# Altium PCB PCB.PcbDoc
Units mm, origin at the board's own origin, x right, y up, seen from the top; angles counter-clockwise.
Board outline 41 x 25.36 mm, 2 copper layers (TOP, BOTTOM), stack 1.586 mm thick; 43 components, 23 nets, 113 pads, 47 vias.
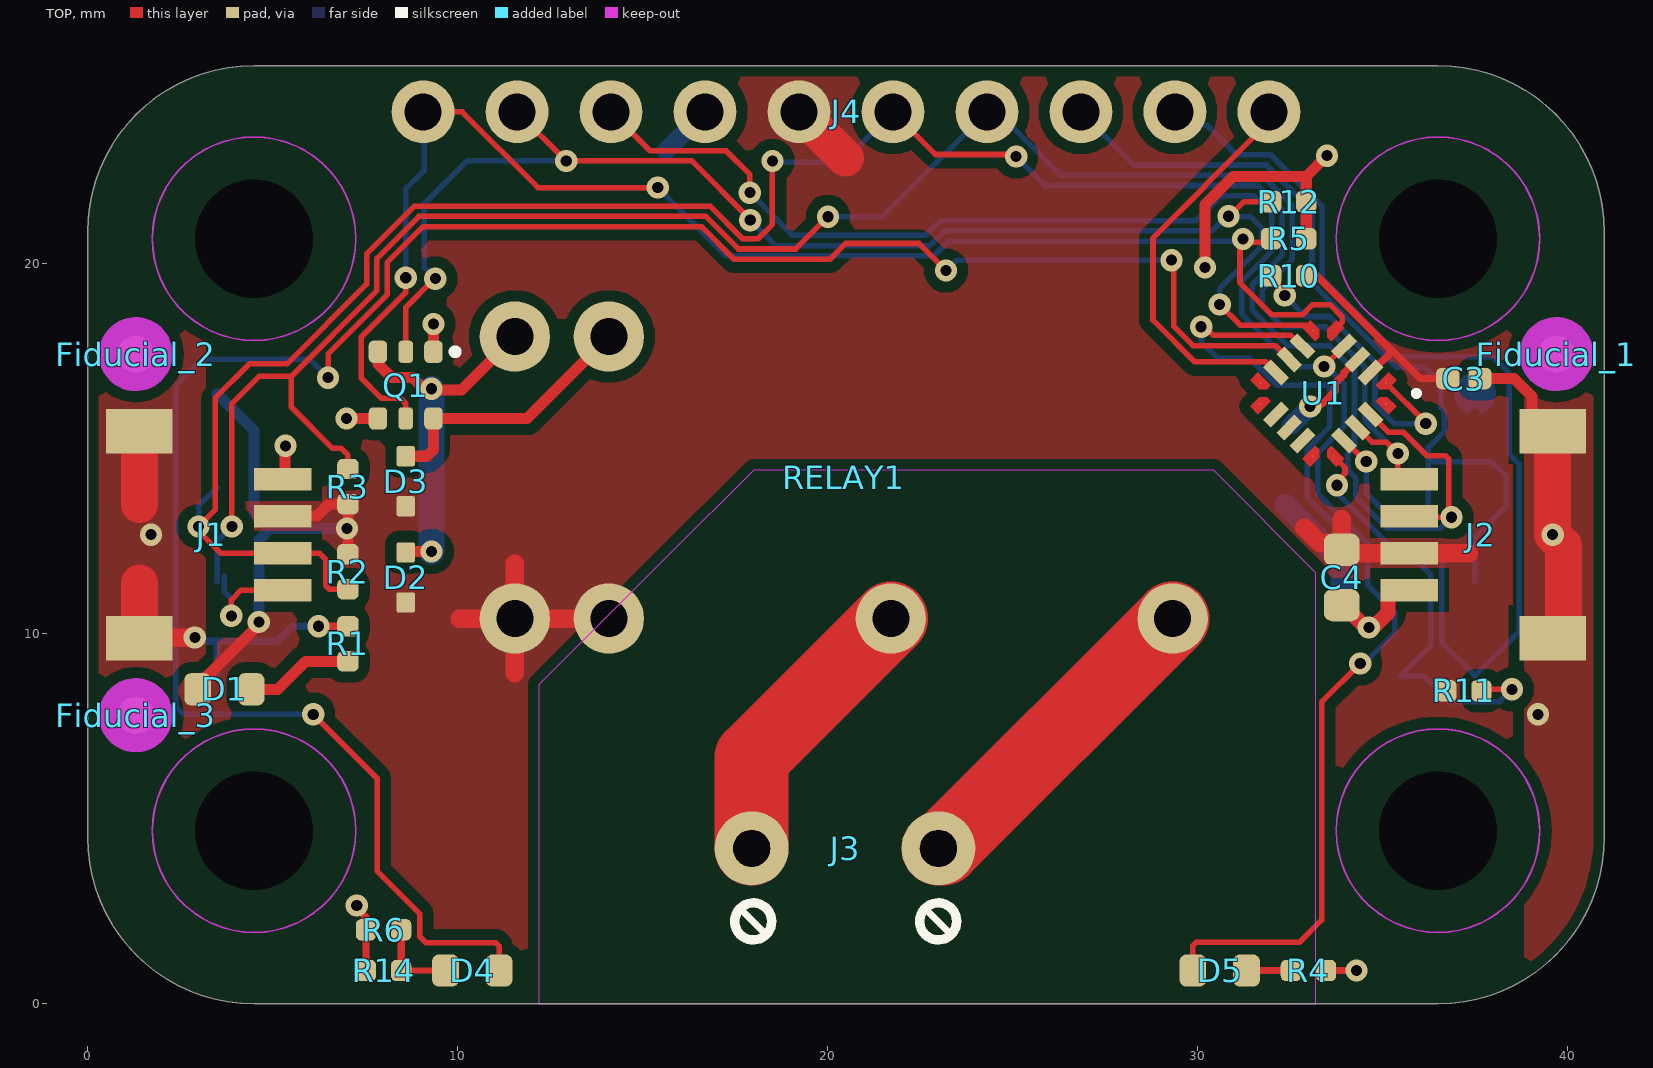
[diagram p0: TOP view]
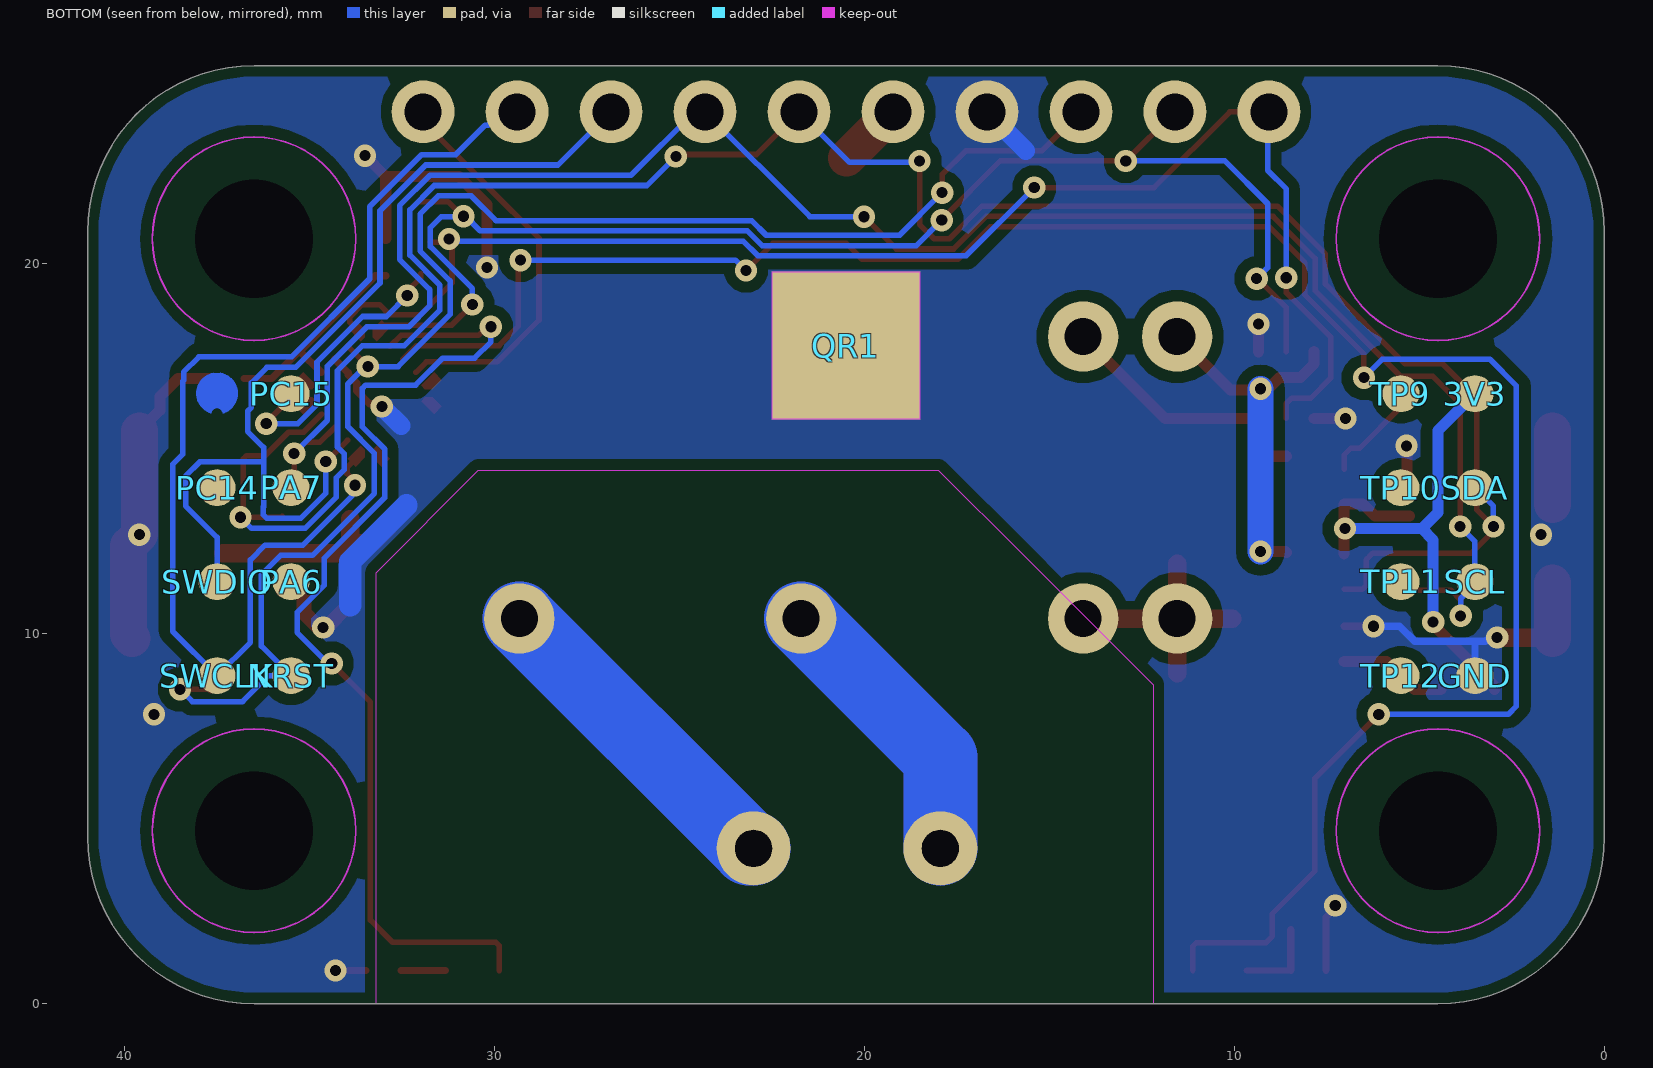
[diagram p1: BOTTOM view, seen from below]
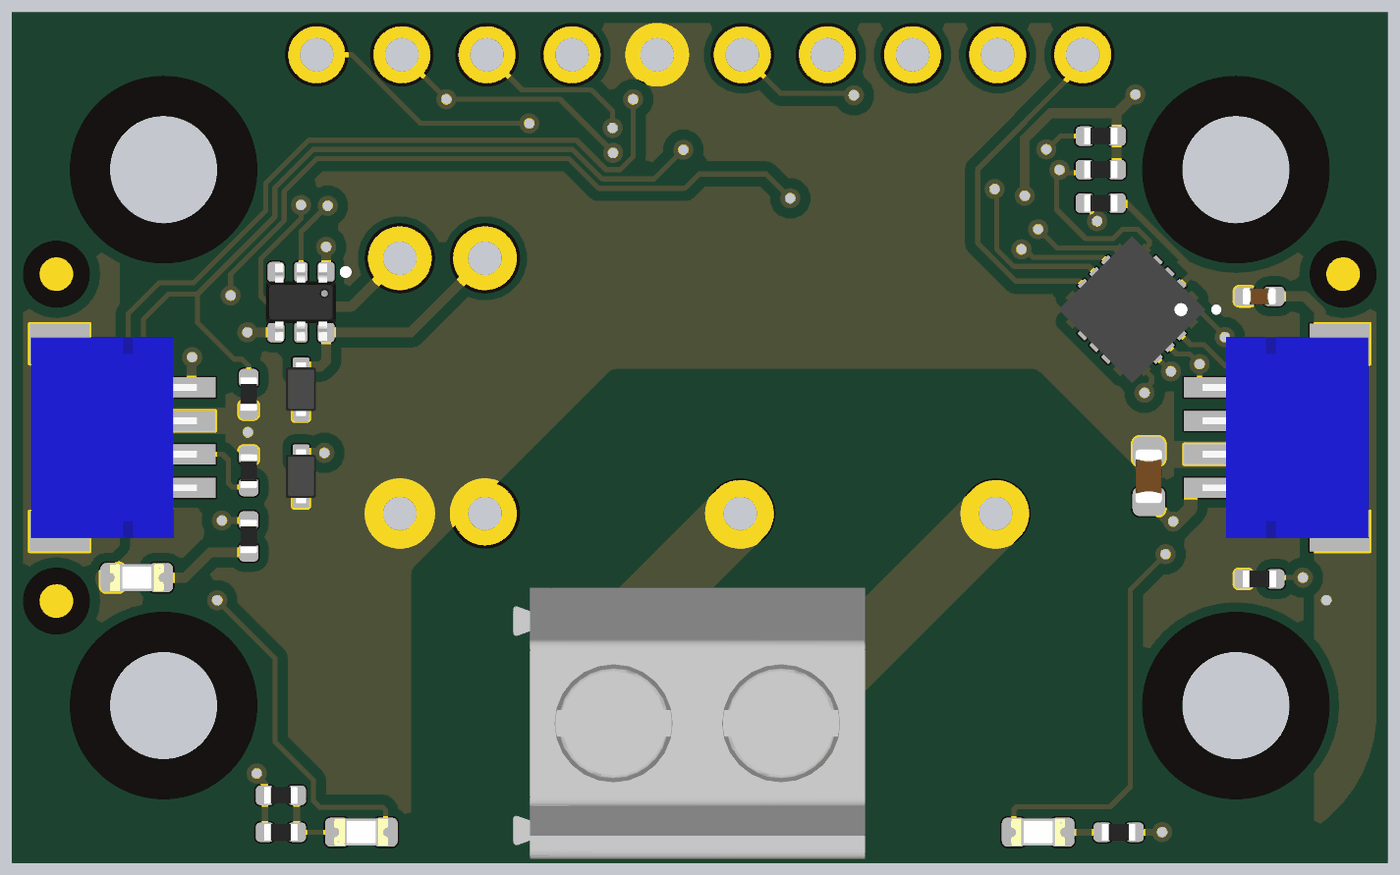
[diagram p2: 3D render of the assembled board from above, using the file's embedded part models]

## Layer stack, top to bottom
Top Solder: solder mask 0.01, Solder Resist, Dk 3.5
TOP: signal copper 0.018
Dielectric: core 1.55, FR-4, Dk 4.8
BOTTOM: signal copper 0.018
Bottom Solder: solder mask 0.01, Solder Resist, Dk 3.5

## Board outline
0,4.5 ccw(c4.5,4.5) 4.5,0 36.5,0 ccw(c36.5,4.5) 41,4.5 41,20.86 ccw(c36.5,20.86) 36.5,25.36 4.5,25.36 ccw(c4.5,20.86) 0,20.86

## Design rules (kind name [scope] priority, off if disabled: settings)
BoardOutlineClearance Mousebites [(ObjectKind = 'Pad') And (Name = 'Free-MOUSEBITE')] p1: gap=0 ignorepadtopadclearanceinfootprint=FALSE
BoardOutlineClearance Silks [(OnLayer('Top Overlay') OR OnLayer('Bottom Overlay'))] p2: gap=0 ignorepadtopadclearanceinfootprint=FALSE
BoardOutlineClearance [All] p3: gap=0.3 ignorepadtopadclearanceinfootprint=FALSE
Clearance CONTACTS_CLEARANCE [InNetClass('CONTACTS') vs NOT((ObjectKind = 'Region') And (Layer = 'MultiLayer'))] p1: gap=2 ignorepadtopadclearanceinfootprint=FALSE
Clearance COPPER_0.3mm [All] p2: gap=0.127 ignorepadtopadclearanceinfootprint=FALSE except(0.3: Arc-Fill Arc-Poly Arc-Region Track-Fill Track-Poly Track-Region SMDPad-Fill SMDPad-Poly SMDPad-Region THPad-Fill THPad-Poly THPad-Region Via-Fill Via-Poly Via-Region Fill-Fill Fill-Poly Fill-Region Poly-Poly Poly-Region Region-Region)
Clearance "Generic clearance 0.15mm" [All] p3: gap=0.15 ignorepadtopadclearanceinfootprint=FALSE
ComponentClearance [All] p1: gap=0.2 collisioncheckmode=3 verticalgap=0 showdistances=TRUE
DiffPairsRouting USB [InDifferentialPairClass('USB')] p1: maxlimit=0.15 minlimit=0.15 mostfreqgap=0.15 toplayer_minwidth=0.15 toplayer_maxwidth=0.21 toplayer_prefwidth=0.2 bottomlayer_minwidth=0.15 bottomlayer_maxwidth=0.21 bottomlayer_prefwidth=0.2 impedanceprofiledriven=TRUE impedanceprofileid={E6B00C31-4C8E-439C-824F-D2B2CDC26F9C} impedanceprofilevalue=90.000000 maxuncoupledlength=12.7
Height [All] p1: minheight=0 maxheight=30 prefheight=12.7
HoleSize [All] p1: absolutevalues=TRUE maxlimit=30 minlimit=0.3 maxpercent=80.000 minpercent=20.000
HoleToHoleClearance [All] p1: gap=0.25 allowstackedmicrovias=FALSE
MinimumAnnularRing [All] p1: minimumring=0.15
PlaneConnect [All] p1: pad.planeconnectstyle=Relief pad.reliefexpansion=0.508 pad.reliefentries=4 pad.reliefconductorwidth=0.254 pad.reliefairgap=0.254 via.planeconnectstyle=Direct via.reliefexpansion=0.508 via.reliefentries=4 via.reliefconductorwidth=0.254 via.reliefairgap=0.254
PolygonConnect PolygonConnect_QR [All] p1: connectstyle=Direct reliefconductorwidth=0.254 reliefentries=4 polygonreliefangle="90 Angle" airgapwidth=0.254
PolygonConnect [All] p2: thpad.connectstyle=Relief thpad.reliefconductorwidth=0.2 thpad.reliefentries=4 thpad.polygonreliefangle="90 Angle" thpad.airgapwidth=0.254 smdpad.connectstyle=Relief smdpad.reliefconductorwidth=0.2 smdpad.reliefentries=4 smdpad.polygonreliefangle="90 Angle" smdpad.airgapwidth=0.254 via.connectstyle=Direct via.reliefconductorwidth=0.254 via.reliefentries=4 via.polygonreliefangle="90 Angle" via.airgapwidth=0.254
RoomDefinition K36 [False vs False] p1: confinementstyle=ConfineIn formatcopy=TRUE lockcomponents=FALSE outline 4.642,2.629 7.942,2.629 7.942,-0.171 4.642,-0.171
RoomDefinition K_1 [False vs False] p2: confinementstyle=ConfineIn formatcopy=TRUE lockcomponents=FALSE outline 7.8,25.6 11.5,25.6 11.5,22.8 7.8,22.8
RoomDefinition TOP [InComponentClass('TOP')] p3: confinementstyle=ConfineIn formatcopy=TRUE lockcomponents=FALSE outline 42.1,5.4 49.2,5.4 49.2,22.3 42.1,22.3
RoutingVias StandardVias [All] p1: holewidth=0.3 width=0.6 viastyle="Through Hole" minholewidth=0.3 minwidth=0.6 maxholewidth=0.3 maxwidth=0.6
SMDToCorner [All] p1: distance=39370
SilkToSilkClearance [All] p1: silktosilkclearance=0.2
SilkToSolderMaskClearance [IsPad] p1: minsilkscreentomaskgap=0.15 clearancetoexposedcopper=TRUE
SolderMaskExpansion VIAtented [IsVia] p1: expansion=0.102 istentingtop=TRUE
SolderMaskExpansion [All] p2: expansion=0.05 istentingtop=FALSE
SupplyNets "Schematic Supply Nets_2" [InNet('+3V3')] p1: voltage=0.000
SupplyNets "Schematic Supply Nets" [InNet('GND')] p2: voltage=0.000
UnConnectedPin [All] p1:
UnRoutedNet [NOT WithinRoom('K36')] p1: checkbadconnections=TRUE
ViasUnderSMD [All] p1: allowed=FALSE
Width StandardTraces [All] p1: maxlimit=5 minlimit=0.15 preferedwidth=0.15 minimp=50.000000 maximp=50.000000 favimp=50.000000
21 further rules are at their usual default settings.

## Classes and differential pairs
net class CONTACTS: NetJ3_1 NetJ3_2
component class U_MICROCONTROLLER: C3 C4 R2 R3 R10 R11 U1
component class TOP: 3V3 D1 D2 D3 D4 D5 Fiducial_1 Fiducial_2 Fiducial_3 GND J1 J2 J3 J4 NRST PA6 PA7 PC14 PC15 Q1 QR1 R1 R4 R5 R6 R12 R14 RELAY1 SCL SDA SWCLK SWDIO TP9 TP10 TP11 TP12

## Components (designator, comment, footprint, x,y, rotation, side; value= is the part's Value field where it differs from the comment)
3V3 "Test point 1.00mm" TP-1.00MM 3.5,16.49 r90 bottom
C3 "0402B104K160CT" CAP-0402 37.2,16.9 r0 top value=100nF
C4 "GRM188R61C475KAAJD" CAP-0603 33.9,11.524 r90 top value=4.7µF
D1 "HSMG-C190" LEDC1608X80N-AK 3.7,8.5 r180 top
D2 "SBD52C05L01" "SOD523 NO POLARITY" 8.6,11.524 r270 top
D3 "SBD52C05L01" "SOD523 NO POLARITY" 8.6,14.124 r270 top
D4 "KPT-1608YC" LEDC1608X80N-AK 10.4,0.9 r0 top
D5 "XHY-STB0603SR" LEDC1608X80N-AK 30.6,0.9 r180 top
Fiducial_1 "Fiducial mark 1mm" "Fiducial mark 1mm-Footprint-1" 39.7,17.56 r270 top
Fiducial_2 "Fiducial mark 1mm" "Fiducial mark 1mm-Footprint-1" 1.3,17.56 r270 top
Fiducial_3 "Fiducial mark 1mm" "Fiducial mark 1mm-Footprint-1" 1.3,7.8 r270 top
GND "Test point 1.00mm" TP-1.00MM 3.5,8.87 r90 bottom
J1 "SM04B-SRSS-TB(LF)(SN)" SM04B-SRSS-TB(LF)(SN)-Footprint-1 3.337,12.68 r90 top locked
J2 "SM04B-SRSS-TB(LF)(SN)" SM04B-SRSS-TB(LF)(SN)-Footprint-1 37.663,12.68 r270 top locked
J3 "DG127-5.0-02P-13-00Z(H)" DG127-5.0-02P-14-00A(H) 20.5,4.2 r180 top
J4 "HEADER TH 2.54mm VERT. 1x010POS" "PIN HEADER 2.54mm VERT. 1x10POS" 20.5,24.11 r0 top locked
NRST "Test point 1.00mm" TP-1.00MM 35.5,8.87 r180 bottom
PA6 "Test point 1.00mm" TP-1.00MM 35.5,11.41 r180 bottom
PA7 "Test point 1.00mm" TP-1.00MM 35.5,13.95 r180 bottom
PC14 "Test point 1.00mm" TP-1.00MM 37.5,13.95 r180 bottom
PC15 "Test point 1.00mm" TP-1.00MM 35.5,16.49 r180 bottom
Q1 "2N7002PS,115" SOT363 8.6,16.724 r180 top
QR1 "QR CODE 4x4mm" "QR CODE 4x4mm" 20.5,17.793 r180 bottom
R1 "CRCW04021K00FKEDC" RES-0402 7.039,9.73 r270 top value=1k
R2 "RC0402FR-074K7L" RES-0402 7.039,11.68 r90 top value=4.7k
R3 "RC0402FR-074K7L" RES-0402 7.039,13.98 r270 top value=4.7k
R4 "CRCW04021K00FKEDC" RES-0402 33,0.9 r180 top value=1k
R5 "RC0402FR-074K7L" RES-0402 32.465,20.68 r0 top value=4.7k
R6 "CRCW04021K00FKEDC" RES-0402 8,2 r0 top value=1k
R10 "RC0402FR-074K7L" RES-0402 32.465,19.68 r180 top value=4.7k
R11 "RC0402FR-074K7L" RES-0402 37.2,8.46 r0 top value=4.7k
R12 "RC0402FR-074K7L" RES-0402 32.465,21.68 r0 top value=4.7k
R14 "CRCW04021K00FKEDC" RES-0402 8,0.9 r0 top value=1k
RELAY1 "HFE60/3-1HT-L2" HFE60/3-1HT-L2 20.5,14.224 r0 top locked
SCL "Test point 1.00mm" TP-1.00MM 3.5,11.41 r90 bottom
SDA "Test point 1.00mm" TP-1.00MM 3.5,13.95 r90 bottom
SWCLK "Test point 1.00mm" TP-1.00MM 37.5,8.87 r180 bottom
SWDIO "Test point 1.00mm" TP-1.00MM 37.5,11.41 r180 bottom
TP9 "Test point 1.00mm" TP-1.00MM 5.5,16.49 r0 bottom
TP10 "Test point 1.00mm" TP-1.00MM 5.5,13.95 r0 bottom
TP11 "Test point 1.00mm" TP-1.00MM 5.5,11.41 r0 bottom
TP12 "Test point 1.00mm" TP-1.00MM 5.5,8.87 r0 bottom
U1 "STM32C011F6U6TR" UFQFPN20 33.4,16.5 r225 top

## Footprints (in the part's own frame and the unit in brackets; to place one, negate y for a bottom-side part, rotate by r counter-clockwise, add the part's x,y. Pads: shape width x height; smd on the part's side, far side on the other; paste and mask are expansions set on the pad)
CAP-0402 [mm] "Chip Capacitor, 2-Leads, Body  0402 (in) 1005 (mm), IPC Medium Density"
  rrect52% 0.63x0.58 smd mask+0.05: 1(-0.435,0) 2(0.435,0)
  body extent -0.5,-0.25 0.5,0.25, height 0.5
CAP-0603 [mm] "Chip Capacitor, Body 0603 imperial,1.6x0.8mm, IPC High Density"
  rrect51% 0.87x0.97 smd mask+0.05: 1(-0.75,0) 2(0.75,0)
  body extent -0.8,-0.4 0.8,0.4, height 0.8
DG127-5.0-02P-14-00A(H) [mm]
  round 2 hole 1 mask+0.05: 1(-2.5,0) 2(2.55,0)
  silkscreen extent -2.99,1.47 3.01,2.47, body extent -4.93,-4 5.57,4.1, height 10
"Fiducial mark 1mm-Footprint-1" [mm]
  round 1 smd paste-10 mask+0.5: 1(0,0)
  TOP keep-out circle w1: c0,0 r0.5
HFE60/3-1HT-L2 [mm]
  round 1.9 hole 1 mask+0.1: 1(-8.95,-3.81) 2(-8.95,3.81) 3(-6.41,-3.81) 4(-6.41,3.81) 5(1.21,-3.81) 6(8.83,-3.81)
  body extent -10.15,-5.55 10.05,5.55, height 10.5
LEDC1608X80N-AK [mm]
  rrect50% 0.72x0.87 smd: A(0.725,0) C(-0.725,0)
  body extent -0.8,-0.4 0.8,0.4, height 0.79
"PIN HEADER 2.54mm VERT. 1x10POS" [mm]
  round 1.7 hole 1 mask+0.1: 1(-11.43,0) 2(-8.89,0) 3(-6.35,0) 4(-3.81,0) 5(-1.27,0) 6(1.27,0) 7(3.81,0) 8(6.35,0) 9(8.89,0) 10(11.43,0)
"QR CODE 4x4mm" [mm]
  rect 4x4 smd paste-2539.97 mask+0.1: PAD(0,0)
  TOP keep-out region: -2,2 2,2 2,-2 -2,-2
RES-0402 [mm] "Chip Resistor, 2-Leads, Body  0402 (in) 1005 (mm), IPC Medium Density"
  rrect51% 0.55x0.58 smd mask+0.05: 1(-0.475,0) 2(0.475,0)
  body extent -0.5,-0.25 0.5,0.25, height 0.34
SM04B-SRSS-TB(LF)(SN)-Footprint-1 [mm]
  rect 0.6x1.55 smd mask+0.05: 1(1.5,-1.937) 2(0.5,-1.937) 3(-0.5,-1.937) 4(-1.5,-1.937)
  rect 1.2x1.8 smd mask+0.05: FIX(-2.8,1.938) FIX(2.8,1.938)
  body extent -3,-2.16 3,2.8, height 2.98
"SOD523 NO POLARITY" [mm]
  rrect25% 0.55x0.5 smd mask+0.05: 1(-0.676,0) 2(0.676,0)
  body extent -0.8,-0.45 0.8,0.45, height 0.7
SOT363 [mm]
  rrect50% 0.5x0.6 smd mask+0.05: 1(-0.75,-0.9) 3(0.75,-0.9) 4(0.75,0.9) 6(-0.75,0.9)
  rrect50% 0.4x0.6 smd mask+0.05: 2(0,-0.9) 5(0,0.9)
  silkscreen extent -1.39,-0.95 -1.29,-0.85, body extent -1.05,-1.15 1.05,1.15, height 1
TP-1.00MM [mm]
  rrect100% 1x1 smd paste-2.54: X(0,0)
UFQFPN20 [mm] "QFN, 20-Leads, Body 3.00x3.00mm, Pitch 0.50mm, IPC Medium Density"
  round 0.025 smd mask+0.05: 1(-1.4,1) 5(-1.4,-1) 6(-1,-1.4) 10(1,-1.4) 11(1.4,-1) 15(1.4,1) 16(1,1.4) 20(-1,1.4)
  rect 0.7x0.3 smd mask+0.05: 2(-1.3,0.5) 3(-1.3,0) 4(-1.3,-0.5) 12(1.3,-0.5) 13(1.3,0) 14(1.3,0.5)
  rect 0.3x0.7 smd mask+0.05: 7(-0.5,-1.3) 8(0,-1.3) 9(0.5,-1.3) 17(0.5,1.3) 18(0,1.3) 19(-0.5,1.3)
  TOP region: -0.85,-1.65 -1.15,-1.65 -1.15,-1.3 -1,-1.15 -0.85,-1.15
  TOP region: 1.65,-0.85 1.65,-1.15 1.3,-1.15 1.15,-1 1.15,-0.85
  TOP region: -1.15,1.3 -1,1.15 -0.85,1.15 -0.85,1.65 -1.15,1.65
  TOP region: -1.15,1 -1.15,0.85 -1.65,0.85 -1.65,1.15 -1.3,1.15
  TOP region: 1,1.15 0.85,1.15 0.85,1.65 1.15,1.65 1.15,1.3
  TOP region: 1.65,1.15 1.65,0.85 1.15,0.85 1.15,1 1.3,1.15
  TOP region: 1.15,-1.65 0.85,-1.65 0.85,-1.15 1,-1.15 1.15,-1.3
  TOP region: -1.3,-1.15 -1.15,-1 -1.15,-0.85 -1.65,-0.85 -1.65,-1.15
  silkscreen extent -1.8,1.75 -1.75,1.8, body extent -1.55,-1.55 1.55,1.55, height 0.6

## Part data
3V3 GND NRST PA6 PA7 PC14 PC15 SCL SDA SWCLK SWDIO TP9 TP10 TP11 TP12: library part UT0013-A.6, Manufacturer="This is not a component"
C3: library part C0012-A.15, "CAP CHIP 0402 100nF 10% 16V X7R", Case Code (Imperial)=0402, Dielectric=X7R, Manufacturer=Walsin, Tolerance=10%, Voltage=16V
C4: library part C0054-A.16, "CAP CHIP 0603 4.7uF 10% 16V X5R", Case Code (Imperial)=0603, Dielectric=X5R, Manufacturer=Murata, Manufacturer 3="Samsung Electro-Mechanics", Part number 2=GRM188R61C475KE11D, Part number 3=CL10A475KO8NNNC, Tolerance=10%, Voltage=16V
D1: library part L0009-A.5, "LED SMD 0603 GREEN/568 15mcd 120^", Manufacturer=Broadcom
D2 D3: library part D0084-A.2, "TVS BIDIRECTIONAL SMD Vr 5V, Vbr min 5.6V, 150W, SOD523", Manufacturer=YAGEO, Voltage Rating (DC)=5V
D4: library part L0008-A.5, "LED SMD 0603 GIA588   8mcd 120^", Manufacturer=Kingbright
D5: library part L0024-A.4, "LED SMD 0603 RED 625nm, water clear, 42 to 88 mcd, 120 degrees, 1.6x0.8x0.6mm", Manufacturer="Shenzen Corehy Technology"
Fiducial_1 Fiducial_2 Fiducial_3: library part UT0023-A.7, "Fiducial mark 1mm clearance 2mm"
J1 J2: library part J0005-A.2, "CONN JST 4POS SIDE 1MM TIN QWIIC", Manufacturer=JST
J3: library part J0519-A.6, "CONN SCREW TERMINAL 2 POS pitch 5mm height 13.6mm BLACK", Manufacturer=Degson
J4: library part J0169-A.9
Q1: library part T0011-A.11, "MOSFET 2N-CH 60V 0.32A SOT363", Manufacturer=Nexperia, Manufacturer 2="Diodes Inc.", Manufacturer Part Number 2=2N7002DW-7-F
QR1: library part QR-0001-A.5, "QR CODE 4x4mm on layer 34 (This is not a component)", Manufacturer="This is not a component"
R1 R4 R6 R14: library part R0007-A.24, "RES CHIP 0402 1k 1% 1/16W", Case Code (Imperial)=0402, Manufacturer=Vishay, Power=62.5mW, Temperature Coefficient=100ppm, Tolerance=1%
R2 R3 R5 R10 R11 R12: library part R0013-A.24, "RES CHIP 0402 4k7 1% 1/16W", Case Code (Imperial)=0402, Manufacturer=YAGEO, Power=62.5mW, Temperature Coefficient=200ppm, Tolerance=1%
RELAY1: library part S0067-A.7, "Relay Bistable Latching Relay, SPST, 250VAC 5A (cos phi 1) 1250VA, 30VDC 5A 150W, Dual coil 30R 3V, 20.2x11.3x10.5mm", Manufacturer="Hongfa Relay"
U1: library part U0390-A.1, "IC Cortex M0, 32b MCU, 32KB Flash, 6KB RAM, VDD 2-3.6V, -40°C to 85°C, QFN20 3x3mm", Manufacturer="ST Microelectronics"

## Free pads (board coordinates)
  round 3 hole 3.2 unplated paste-2539.97 mask+1.3: MH(4.5,4.68) MH(4.5,20.68) MH(36.5,4.68) MH(36.5,20.68)

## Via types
v1: diameter 0.6, hole 0.3, TOP to BOTTOM, tented both sides, 47 vias

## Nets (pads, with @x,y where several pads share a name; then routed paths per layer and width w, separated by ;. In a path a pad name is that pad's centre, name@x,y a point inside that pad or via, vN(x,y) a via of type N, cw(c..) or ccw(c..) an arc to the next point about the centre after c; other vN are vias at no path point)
+3V3: 3V3.X C3.1 C4.2 D1.A D2.2 D3.2 J1.2 J2.2 J4.5 R2.2 R3.2 R10.1 R11.1 RELAY1.1 RELAY1.3 U1.2 | length 34.8
  TOP w0.2: R10.1 33.225,19.68 33.607,19.298 35.263,17.643 ; U1.2@34.686,17.066 35.263,17.643 ; C3.1 36.022,16.9 35.271,17.651 35.263,17.643
  TOP w0.3: D1.A 2.975,8.591 4.63,10.246 v1(4.63,10.322) ; J1.2 6.2,13.18 6.525,13.505 R3.2 R2.2 ; v1@6.979,12.88 v1(7.015,12.843)
  TOP w0.5: 10.064,10.414 RELAY1.1 ; 11.55,8.928 RELAY1.1 ; 11.55,11.9 RELAY1.1 ; RELAY1.3 RELAY1.1 ; 32.892,12.868 33.315,12.445 33.729,12.445 C4.2 33.9,13.1 ; C4.2@33.906,12.18 J2.2 37.328,12.18
  TOP w1: J4.5 20.48,22.86
  BOTTOM w0.3: 3V3.X 4.5,15.49 4.5,13.28 4.937,12.843 ; v1(4.63,10.322) 4.63,12.536 4.937,12.843 ; v1(7.015,12.843) 4.937,12.843
GND: C3.2 C4.1 GND.X J1.1 J1.FIX J2.1 J2.FIX J4.4 Q1.1 Q1.4 QR1.PAD R1.1 R4.1 R5.2 R6.1 R12.2 R14.1 U1.3 | length 41.5
  TOP w0.2: v1(6.239,10.205) R1.1 ; v1(7.277,2.653) 7.277,2.583 7.525,2.335 R14.1 ; v1(33.046,16.146) 33.123,16.223 33.381,16.223 33.727,16.569 33.727,16.781 33.952,17.005 33.952,17.052 U1.3 ; R4.1 v1(34.3,0.9)
  TOP w0.3: J1.1 5.332,14.238 5.332,15.061 v1(5.352,15.081) ; v1(7,15.824) Q1.4@7.85,15.824 ; Q1.1 v1(9.35,18.374) ; v1(30.2,19.9) 30.2,21.6 30.964,22.364 32.94,22.364 ; R5.2 R12.2 32.94,22.364 ; v1(33.5,22.924) 32.94,22.364 ; C3.2 38.554,16.9 39.037,16.417 39.037,16.043 J2.FIX@39.601,15.48
  TOP w0.4: C4.1@33.9,10.674 34.05,10.674 34.511,10.213 34.593,10.213 v1(34.631,10.175) 34.669,10.213 34.793,10.213 35.151,10.571 35.151,11.08 35.251,11.18 J2.1
  TOP w0.5: J1.FIX@1.399,9.88 1.419,9.9 v1(2.9,9.9)
  TOP w1: J1.FIX@1.399,9.88 1.399,11.379 ; 1.399,13.499 J1.FIX@1.399,15.48 ; J2.FIX@39.601,15.48 v1(39.601,12.68) 39.896,12.385 39.896,9.98 J2.FIX@39.796,9.88
  BOTTOM w0.2: v1(2.9,9.9) 2.977,9.823 3.188,9.823 3.217,9.795 5.129,9.795 5.539,10.205 v1(6.239,10.205) ; GND.X 3.5,9.784
  BOTTOM w0.5: 15.638,23.058 J4.4 ; 32.524,15.624 v1(33.046,16.146)
  BOTTOM w0.6: 32.378,13.474 33.9,11.952 33.9,10.774
  other v1: 39.2,7.824 1.713,12.68
NetD1_C: D1.C R1.2 | length 2.9
  TOP w0.3: D1.C 5.134,8.5 5.889,9.255 R1.2
NetD2_1: D2.1 Q1.3 RELAY1.2 | length 10
  TOP w0.3: Q1.3 7.85,17.3 8.219,16.931 8.781,16.931 9.03,16.681 v1@9.3,16.681 ; D2.1 8.624,12.224 v1(9.3,12.224) ; v1(9.3,16.624) 9.332,16.592 10.108,16.592 RELAY1.2
  BOTTOM w0.7: v1(9.3,12.224) v1(9.3,16.624)
NetD3_1: D3.1 Q1.6 RELAY1.4 | length 7.3
  TOP w0.3: D3.1 9.174,14.8 9.35,14.976 Q1.6 11.88,15.824 RELAY1.4
NetD4_C: D4.C R6.2 R14.2 | length 2.3
  TOP w0.15: R14.2 D4.C
  TOP w0.2: R14.2 R6.2
NetD5_C: D5.C R4.2 | length 1.2
  TOP w0.2: D5.C R4.2
NetJ3_1: J3.1 RELAY1.6 | length 17.8
  TOP w2: J3.1 23.116,4.2 RELAY1.6
  BOTTOM w2: J3.1 23.116,4.2 RELAY1.6
NetJ3_2: J3.2 RELAY1.5 | length 15.5
  TOP w2: J3.2 17.95,6.654 RELAY1.5
  BOTTOM w2: J3.2 17.95,6.654 RELAY1.5
NetU1_10: U1.10
NetU1_14: U1.14
NetU1_15: U1.15
PA0_1: J4.1 Q1.5 R5.1 U1.5 | length 39.5
  TOP w0.15: Q1.5 8.6,16.224 8.452,16.372 7.936,16.372 7.398,16.91 7.398,18.022 8.6,19.224 v1(8.6,19.624) ; J4.1 9.339,23.841 9.608,24.11 10.122,24.11 12.172,22.06 v1(15.411,22.06) ; R5.1@31.742,20.59 31.15,20.59 31.15,19.488 32.017,18.622 32.831,18.622 33.11,18.9 33.578,18.9 33.913,18.565 33.913,18.427 U1.5
  BOTTOM w0.15: v1(8.6,19.624) 8.598,19.626 8.598,22.022 9.1,22.524 9.1,24.08 J4.1 ; v1(15.411,22.06) 17.253,20.218 22.884,20.218 23.283,20.617 31.177,20.617 v1(31.234,20.674)
PA1_1: J4.2 Q1.2 R12.1 U1.6 | length 37.5
  TOP w0.15: Q1.2 8.6,18.824 9.376,19.6 v1(9.4,19.6) ; J4.2 v1(12.939,22.781) 16.333,22.781 17.913,21.201 v1(17.913,21.18) ; v1(30.6,18.9) 31.155,18.345 32.97,18.345 U1.6 ; v1(30.842,21.286) 30.868,21.286 31.262,21.68 R12.1
  BOTTOM w0.15: v1(9.4,19.6) 9.1,19.9 9.1,21.624 10.257,22.781 v1(12.939,22.781) ; v1(17.913,21.18) 18.598,20.495 22.77,20.495 23.168,20.894 30.385,20.894 30.778,21.286 v1(30.842,21.286) 30.856,21.272 31.442,21.272 31.736,20.978 31.736,20.465 30.6,19.329 v1(30.6,18.9)
PA2_1: D5.A U1.7 | length 28.3
  TOP w0.15: D5.A 29.875,1.574 29.963,1.662 32.751,1.662 33.354,2.265 33.354,8.154 v1(34.4,9.2) ; v1(30.1,18.3) 30.201,18.3 30.433,18.068 32.525,18.068 32.82,17.773 U1.7
  BOTTOM w0.15: v1(30.1,18.3) 30.1,17.89 30.537,17.453 31.399,17.453 32.13,16.722 33.482,16.722 33.57,16.634 33.57,15.596 32.968,14.994 32.968,13.681 34.6,12.048 34.6,11.317 35.338,10.579 35.338,10.038 34.5,9.2 v1(34.4,9.2)
PA3_1: D4.A U1.8 | length 58.8
  TOP w0.15: v1(6.1,7.824) 7.827,6.097 7.827,3.586 8.975,2.439 8.975,1.825 9.154,1.646 11.037,1.646 11.125,1.558 D4.A ; v1(6.5,16.924) 6.5,17.562 8.098,19.16 8.098,20.032 9.07,21.004 16.595,21.004 17.475,20.124 20.065,20.124 20.49,20.55 22.474,20.55 v1(23.2,19.824) ; v1(29.3,20.1) 29.36,20.04 29.36,18.309 29.878,17.791 32.109,17.791 U1.8
  BOTTOM w0.15: v1(6.1,7.824) 2.6,7.824 2.378,8.046 2.378,16.702 3.1,17.424 6,17.424 v1(6.5,16.924) ; v1(23.2,19.824) 23.214,19.824 23.49,20.1 v1(29.3,20.1)
PA4_1: J4.10 U1.9 | length 10.8
  TOP w0.15: J4.10 31.93,23.844 30.2,22.114 30.2,22.098 28.798,20.696 28.798,18.479 29.926,17.351 31.842,17.351 U1.9
PA13_SWDIO_1: J4.9 SWCLK.X U1.16 | length 30.2
  TOP w0.15: U1.16@33.683,14.798 33.987,14.494 33.987,14.33 33.771,14.114 v1(33.771,14.017)
  BOTTOM w0.15: J4.9 29.809,24.11 30.17,23.75 30.25,23.75 31.051,22.949 31.974,22.949 33.373,21.55 33.373,19.597 35.485,17.485 37.993,17.485 38.404,17.074 38.404,16.853 38.431,16.825 38.431,14.851 38.7,14.583 38.7,10.07 SWCLK.X 36.6,9.77 36.6,12 36.2,12.4 35.181,12.4 33.857,13.724 33.857,13.931 v1(33.771,14.017)
PA14_SWCLK_BOOT0_1: J4.8 SWDIO.X U1.17 | length 26.9
  TOP w0.15: U1.17 33.978,15.227 34.548,14.657 v1(34.561,14.657)
  BOTTOM w0.15: J4.8 28.288,22.672 31.859,22.672 33.096,21.436 33.096,19.483 35.378,17.2 36.152,17.2 36.57,16.782 36.57,16.118 36.672,16.016 36.672,15.472 36.24,15.04 36.24,14.652 ; v1(34.561,14.657) 34.561,13.804 35.236,13.129 36.159,13.129 36.247,13.217 36.247,13.44 ; 36.24,13.44 36.24,14.652 ; SWDIO.X 37.5,12.605 38.35,13.455 38.35,14.266 37.964,14.652 36.24,14.652
PC15_2: R10.2 U1.1 | length 8.2
  TOP w0.15: R10.2@31.999,19.735 31.999,19.62 32.358,19.261 v1(32.358,19.144) ; U1.1 36.17,15.71 v1(36.17,15.68)
  BOTTOM w0.15: v1(32.358,19.144) 32.925,18.577 33.564,18.577 34.798,17.344 34.798,16.199 35.317,15.68 v1(36.17,15.68)
PF2_N\R\S\T\_1: J4.3 NRST.X R11.2 U1.4 | length 42.1
  TOP w0.15: J4.3 15.202,23.058 17.262,23.058 17.9,22.42 v1(17.9,21.924) ; v1(33.425,17.224) 33.425,17.228 33.966,17.769 U1.4 ; R11.2 37.715,8.5 v1(38.5,8.5)
  BOTTOM w0.15: v1(17.9,21.924) 19.052,20.772 22.655,20.772 23.053,21.171 29.96,21.171 30.63,21.841 31.515,21.841 32.013,21.343 32.013,20.35 31.199,19.537 31.199,18.633 32.608,17.224 33.493,17.224 33.967,16.75 33.967,15.601 33.245,14.879 33.245,13.798 34.92,12.123 35.78,12.123 36.3,11.603 36.3,9.67 NRST.X 36.11,8.87 36.812,8.168 38.168,8.168 v1(38.5,8.5)
SCL_1: J1.4 J2.4 J4.7 R3.1 SCL.X U1.18 | length 57
  TOP w0.15: v1(3.886,10.486) 3.886,10.916 4.15,11.18 J1.4 ; v1(3.9,12.9) 3.9,16.223 4.638,16.96 5.506,16.96 ; R3.1 7.039,14.83 6.849,15.02 6.613,15.02 5.506,16.126 5.506,16.96 ; v1(20.011,21.274) 19.138,20.401 17.59,20.401 16.71,21.281 8.955,21.281 7.821,20.147 7.821,19.275 5.506,16.96 ; U1.18 34.727,15.173 35.115,15.173 v1(35.415,14.874) 35.415,14.405 35.64,14.18 J2.4
  BOTTOM w0.15: SCL.X 3.5,12.5 v1(3.9,12.9) ; SCL.X@3.694,11.557 3.694,11.14 3.886,10.948 v1(3.886,10.486) ; v1(20.011,21.274) 21.474,21.274 J4.7 24.6,24.11 26.315,22.395 31.745,22.395 32.567,21.573 32.567,21.419 32.567,20.121 31.753,19.307 31.753,18.862 32.315,18.3 33.45,18.3 34.521,17.229 34.521,15.768 v1(35.415,14.874)
SDA_1: J1.3 J2.3 J4.6 R2.1 SDA.X U1.19 | length 64
  TOP w0.15: R2.1 6.539,11.205 6.439,11.305 6.439,12.005 6.339,12.105 6.264,12.18 J1.3 3.598,12.18 3.186,12.592 3,12.778 v1(3,12.9) 3.448,13.348 3.448,16.374 4.371,17.297 5.389,17.297 7.544,19.451 7.544,20.261 8.841,21.558 16.825,21.558 17.705,20.678 18.121,20.678 18.511,21.068 v1(18.511,22.781) ; J4.6 22.924,22.956 25.044,22.956 v1(25.1,22.9) ; U1.19 35.157,15.45 35.562,15.45 36.197,14.816 36.699,14.816 36.786,14.728 36.786,13.233 v1(36.867,13.152) 35.753,13.152 J2.3@35.732,13.173
  BOTTOM w0.15: v1(3,12.9) 3,13.45 SDA.X ; v1(18.511,22.781) 18.551,22.74 20.4,22.74 J4.6 ; v1(25.1,22.9) 25.882,22.118 31.63,22.118 32.29,21.458 32.29,21.304 32.29,20.235 31.476,19.422 31.476,18.747 32.442,17.781 33.577,17.781 34.244,17.114 34.244,15.05 34.059,14.865 34.059,14.439 34.284,14.214 34.284,13.689 35.121,12.852 36.567,12.852 v1(36.867,13.152)
pads on no net: Fiducial_1.1 Fiducial_2.1 Fiducial_3.1 PA6.X PA7.X PC14.X PC15.X TP9.X TP10.X TP11.X TP12.X U1.11 U1.12 U1.13 U1.20

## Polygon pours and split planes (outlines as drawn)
+3V3 on TOP "C" (solid, remove dead copper, pour order 8): 0,4.5 ccw(c4.5,4.5) 4.5,0 36.5,0 ccw(c36.5,4.5) 41,4.5 41,20.86 ccw(c36.5,20.86) 36.5,25.36 4.5,25.36 ccw(c4.5,20.86) 0,20.86
GND on TOP "NONET_L04_P-001" (solid, remove dead copper, pour order 6): 41,25.36 41,0 38.828,0 38.828,25.36
GND on TOP "NONET_L04_P-001" (solid, remove dead copper, pour order 5): 0,25.36 0,0 3.2,0 3.2,25.36
GND on BOTTOM "NONET_L04_P-001" (solid, remove dead copper, pour order 9): 0,4.5 ccw(c4.5,4.5) 4.5,0 36.5,0 ccw(c36.5,4.5) 41,4.5 41,20.86 ccw(c36.5,20.86) 36.5,25.36 4.5,25.36 ccw(c4.5,20.86) 0,20.86

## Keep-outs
Keep-Out Layer:
  circle w0.05: c4.5,4.68 r2.75
  circle w0.05: c36.5,4.68 r2.75
  circle w0.05: c36.5,20.68 r2.75
  circle w0.05: c4.5,20.68 r2.75
  region: 18.004,14.424 15.7,12.12 12.2,8.62 12.2,0 33.2,0 33.2,11.658 30.434,14.424 28.6,14.424

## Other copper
BOTTOM:
  region: 441 vertices and 0 holes, not listed, extent 36.945,15.962 38.056,17.054

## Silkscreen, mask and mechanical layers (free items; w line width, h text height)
Route Tool Path:
  lines w2: -1,8.498 -1,16.86 ; 42,8.498 42,16.86 ; -1,4.5 ccw(c4.5,4.5) 4.498,-1 ; -1,4.5 -1,4.5 ; -1,20.86 cw(c4.5,20.86) 4.5,26.36 ; -1,20.86 -1,20.86 ; 4.498,-1 ccw(c4.5,4.5) 4.5,-1 ; 4.498,-1 ccw(c4.5,0) 4.5,-1 ; 4.5,-1 36.5,-1 ; 4.5,26.36 36.5,26.36 ; 4.5,26.36 4.5,26.36 ; 36.5,-1 ccw(c36.5,4.5) 36.502,-1 ; 36.5,-1 ccw(c36.5,0) 36.502,-1 ; 36.5,26.36 cw(c36.5,25.36) 36.502,26.36 ; 36.5,26.36 cw(c36.5,20.86) 36.502,26.36 ; 36.502,-1 ccw(c36.5,4.5) 42,4.498 ; 36.502,26.36 cw(c36.5,20.86) 42,20.863 ; 42,4.498 ccw(c41,4.5) 42,4.5 cw(c36.5,4.5) 42,4.498 ; 42,20.863 cw(c41,20.86) 42,20.86 ccw(c36.5,20.86) 42,20.863
Board:
  lines w0.05: 36.5,0 ccw(c36.5,0) 36.5,0 ; 36.5,0 ccw(c36.5,0) 36.5,0 ; 36.5,0 ccw(c36.5,4.5) 41,4.5 41,20.86 ccw(c36.5,20.86) 36.5,25.36 4.5,25.36 ccw(c4.5,20.86) 0,20.86 0,4.5 ccw(c4.5,4.5) 4.5,0 22,0 36.5,0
